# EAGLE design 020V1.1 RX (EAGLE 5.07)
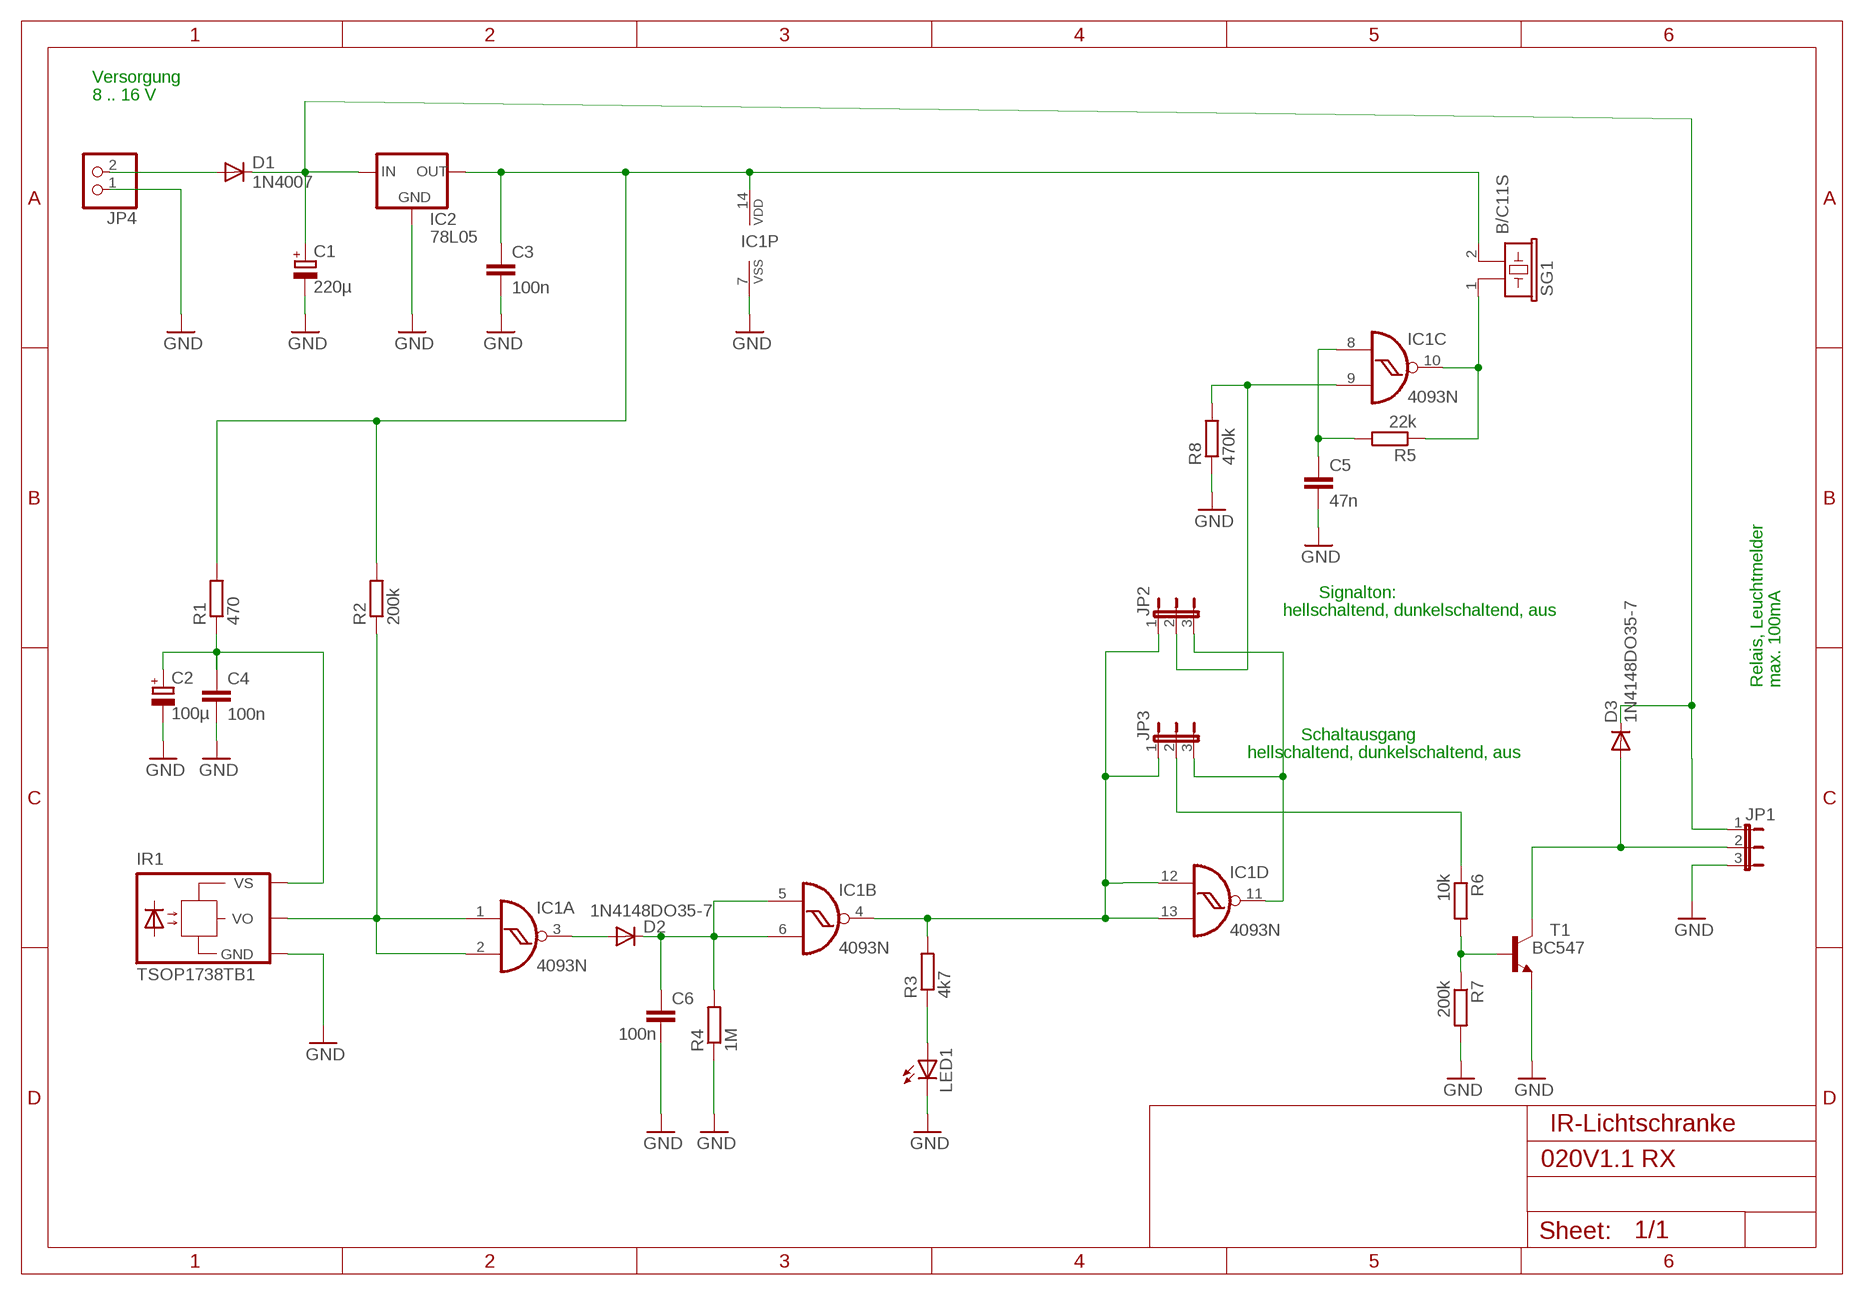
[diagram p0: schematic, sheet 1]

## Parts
C1  220µ  CPOL-EUE2.5-7  [E2,5-7]
C2  100µ  CPOL-EUE2.5-7  [E2,5-7]
C3  100n  C-EU050-025X075  [C050-025X075]
C4  100n  C-EU050-025X075  [C050-025X075]
C5  47n  C-EU050-025X075  [C050-025X075]
C6  100n  C-EU050-025X075  [C050-025X075]
D1  1N4007  1N4004  [DO41-10]
D2  1N4148DO35-7  [DO35-7]
D3  1N4148DO35-7  [DO35-7]
IC1  4093N  [DIL14]
IC2  78L05  78LXX5MM  [TO92-5]
IR1  TSOP1738TB1  [TSOP17_TB1]
JP1  JP2E  [JP2]
JP2  JP2E  [JP2]
JP3  JP2E  [JP2]
JP4  PINHD-1X2  [1X02]
LED1  LED3MM  [LED3MM]
R1  470  R-EU_0204/7  [0204/7]
R2  200k  R-EU_0204/7  [0204/7]
R3  4k7  R-EU_0204/7  [0204/7]
R4  1M  R-EU_0204/7  [0204/7]
R5  22k  R-EU_0204/7  [0204/7]
R6  10k  R-EU_0204/7  [0204/7]
R7  200k  R-EU_0204/7  [0204/7]
R8  470k  R-EU_0204/7  [0204/7]
SG1  B/C11S  [B/C11S]
T1  BC547  [TO92-5]

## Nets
GND: C1.- C2.- C3.2 C4.2 C5.2 C6.2 IC1.7(P:VSS) IC2.2(GND) IR1.GND JP1.3 JP4.1 LED1.K(C) R4.1 R7.2 R8.1 T1.1(E)
N$1: D1.A JP4.2
N$2: C1.+ D1.C D3.C IC2.1(IN) JP1.1
N$3: C3.1 IC1.14(P:VDD) IC2.3(OUT) R1.2 R2.2 SG1.2
N$4: C2.+ C4.1 IR1.VS R1.1
N$5: IC1.1(A:I0) IC1.2(A:I1) IR1.VO R2.1
N$6: D2.A IC1.3(A:O)
N$7: C6.1 D2.C IC1.5(B:I0) IC1.6(B:I1) R4.2
N$8: LED1.A R3.1
N$9: IC1.4(B:O) IC1.12(D:I0) IC1.13(D:I1) JP2.1 JP3.1 R3.2
N$11: C5.1 IC1.8(C:I0) R5.2
N$12: IC1.10(C:O) R5.1 SG1.1
N$13: JP3.2 R6.1
N$14: D3.A JP1.2 T1.3(C)
N$15: IC1.9(C:I1) JP2.2 R8.2
N$16: IC1.11(D:O) JP2.3 JP3.3
N$17: R6.2 R7.1 T1.2(B)

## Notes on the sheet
- Versorgung
- 8 .. 16 V
- Signalton:
- hellschaltend, dunkelschaltend, aus
- Relais, Leuchtmelder | max. 100mA
- Schaltausgang
- hellschaltend, dunkelschaltend, aus
- IR-Lichtschranke

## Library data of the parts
C1 C2 = rcl:CPOL-EU: POLARIZED CAPACITOR, European symbol
C3-C6 = rcl:C-EU: CAPACITOR, European symbol
D1 = diode:1N4004: DIODE
D2 D3 = diode:1N4148: DIODE
IC1 = 40xx:4093: Quad 2-input NAND schmitt trigger
IC2 = armin:78LXX: VOLTAGE REGULATOR
IR1 = telefunken:TSOP17*TB1: TSOP17..TB1 IR Receiver Modules for Remote Control Systems Source: http://www.vishay.com/docs/82042/82042.pdf
JP1-JP3 = jumper:JP2E: JUMPER
JP4 = pinhead:PINHD-1X2: PIN HEADER
LED1 = led:LED: LED
R1-R8 = rcl:R-EU_: RESISTOR, European symbol
SG1 = buzzer:B/C11S: BUZZER
T1 = armin:BC547: NPN TRANSISTOR

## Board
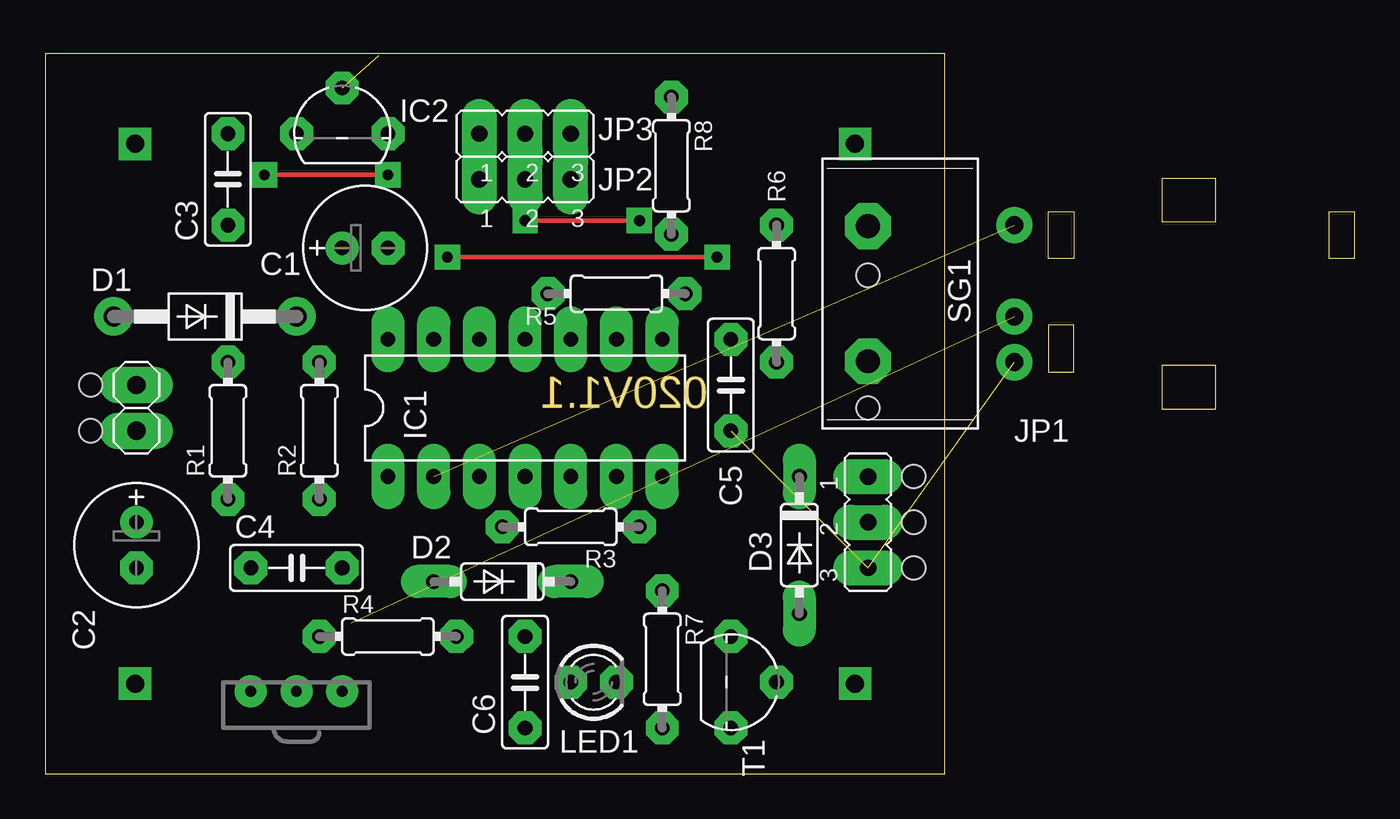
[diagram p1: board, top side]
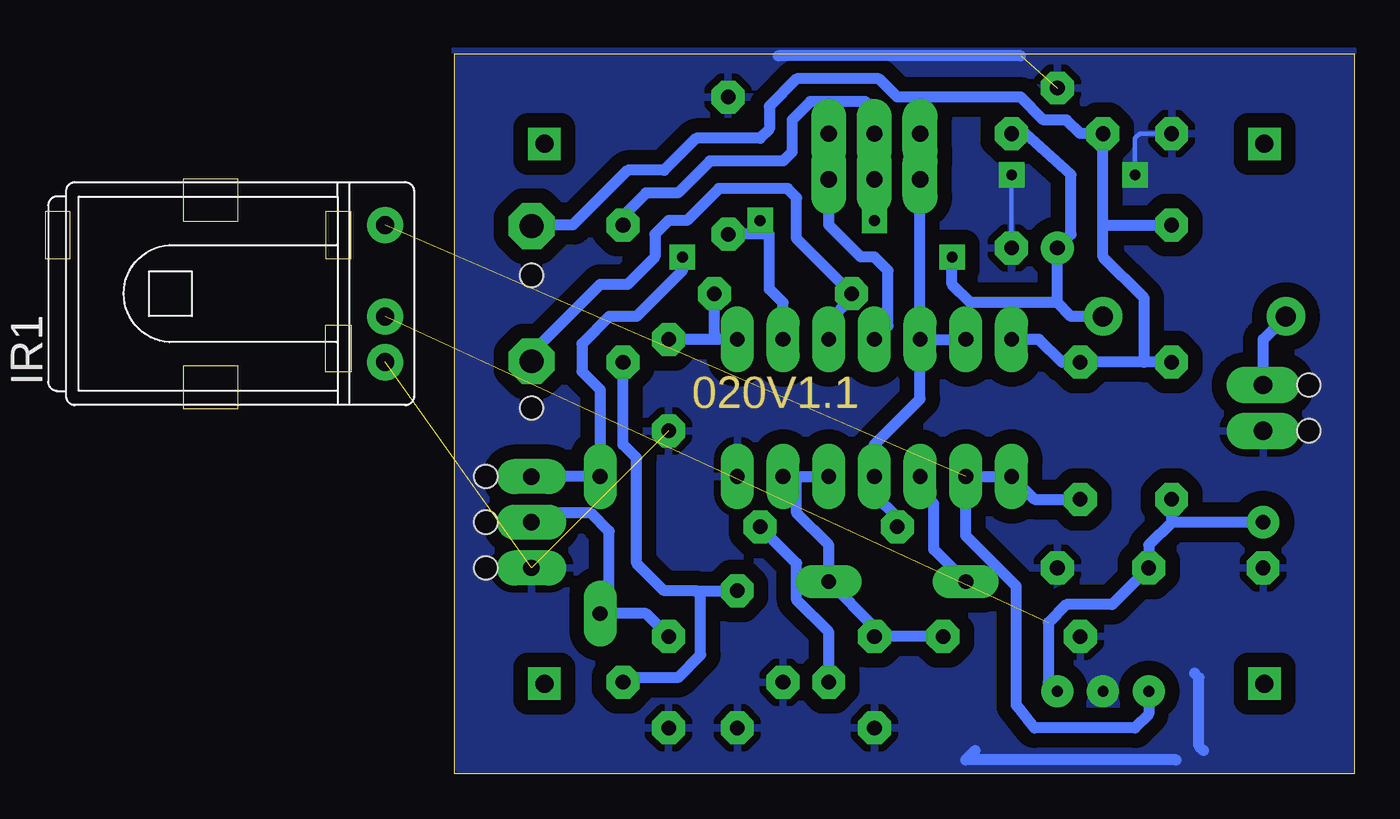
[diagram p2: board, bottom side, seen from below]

Size 72.75 x 40 mm. Coordinates in mm from the lower left corner, seen from the top.
Outline: 0,0 50,0 50,40 0,40 0,0
Copper layers (1*16): Top 0.035mm / dielectric 1.5mm / Bottom 0.035mm
Design rules "default *": minimum track width 10mil, minimum drill 24mil, track to track 32mil, track to pad 32mil, pad to pad 25mil, via to via 25mil, smd to smd 8mil, copper to edge 1mil, drill to drill 8mil, minimum pad ring 20mil, minimum via ring 16mil, stop-mask expansion 4mil, vias tented up to drill 0mil, thermal gap 16mil
Holes 1.3 mm at 2.54,21.59 2.54,19.05 45.72,27.69 45.72,20.32 48.26,13.97 48.26,11.43 48.26,13.97 48.26,16.51

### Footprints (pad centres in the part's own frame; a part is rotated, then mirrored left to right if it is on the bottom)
E2,5-7 = drill 0.813 pad 1.6 round: + -1.27,0 | drill 0.813 pad 1.6 octagon: - 1.27,0
C050-025X075 = drill 0.813 octagon: 1 -2.54,0; 2 2.54,0
DO41-10 = drill 1.118 round: A 5.08,0; C -5.08,0
DO35-7 = drill 0.813 long: A 3.81,0; C -3.81,0
DIL14 = drill 0.813 long: 1 -7.62,-3.81; 2 -5.08,-3.81; 3 -2.54,-3.81; 4 0,-3.81; 5 2.54,-3.81; 6 5.08,-3.81; 7 7.62,-3.81; 8 7.62,3.81; 9 5.08,3.81; 10 2.54,3.81; 11 0,3.81; 12 -2.54,3.81; 13 -5.08,3.81; 14 -7.62,3.81
TO92-5 = drill 0.813 octagon: 1 2.54,0; 2 0,2.54; 3 -2.54,0
TSOP17_TB1 = drill 1 pad 1.676 round: GND 0,-3.81; VO 0,3.81; VS 0,-1.27
JP2 = drill 0.914 long: 1 -2.54,0; 2 0,0; 3 2.54,0
1X02 = drill 1.016 long: 1 -1.27,0; 2 1.27,0
LED3MM = drill 0.813 octagon: A -1.27,0; K 1.27,0
0204/7 = drill 0.813 octagon: 1 -3.81,0; 2 3.81,0
B/C11S = drill 1.321 pad 2.54 octagon: 1 -3.759,0; 2 3.759,0

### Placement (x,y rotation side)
C1  17.78,29.21 0 top
C2  5.08,12.7 270 top
C3  10.16,33.02 90 top
C4  13.97,11.43 0 top
C5  38.1,21.59 270 top
C6  26.67,5.08 270 top
D1  8.89,25.4 180 top
D2  25.4,10.67 180 top
D3  41.91,12.7 270 top
IC1  26.67,20.32 0 top
IC2  16.51,35.56 0 top
IR1  53.85,26.67 0 bottom
JP1  45.72,13.97 270 top
JP2  26.67,33.02 0 top
JP3  26.67,35.56 0 top
JP4  5.08,20.32 90 top
LED1  30.48,5.08 0 top
R1  10.16,19.05 90 top
R2  15.24,19.05 90 top
R3  29.21,13.72 180 top
R4  19.05,7.62 0 top
R5  31.75,26.67 0 top
R6  40.64,26.67 270 top
R7  34.29,6.35 270 top
R8  34.8,33.78 270 top
SG1  45.72,26.67 90 top
T1  38.1,5.08 270 top

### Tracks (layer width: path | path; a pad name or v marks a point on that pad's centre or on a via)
GND  (via drill 0.6, 0.6 pad 1.78)  (3 unrouted)
  Top 0.254: v12.19,33.27 v19.05,33.27
  Bottom 0.254: v19.05,33.27 C1.- | v12.19,33.27 12.19,35.31 11.94,35.56 C3.2
  Bottom 0.61: 21.08,1.27 21.59,0.76 9.91,0.76 | 8.89,5.59 8.64,5.33 8.64,1.52 8.38,1.27 | 18.54,39.88 32,39.88
  other vias: 13.97,4.57
  pour Bottom: 0,40.13 50.04,40.13 50.04,0.51 49.78,0.25 0,0.25 0,37.59 0.25,37.85
  pour Bottom: 24.89,21.08 26.42,19.56 36.83,19.3 37.34,21.08 37.34,23.11 24.89,23.11
N$1
  Bottom 0.61: JP4.2 5.08,24.13 D1.A
N$2  (via drill 0.6)
  Top 0.254: v22.35,28.7 v37.34,28.7
  Bottom 0.61: IC2.1 18.29,35.56 15.75,33.27 15.75,29.97 C1.+ 16.51,26.16 | 16.51,26.16 15.75,25.4 D1.C | v37.34,28.7 37.34,27.94 39.88,25.4 41.4,25.4 42.93,23.88 42.93,22.35 41.91,21.34 D3.C JP1.1 | 16.51,26.16 21.34,26.16 22.35,27.18 v22.35,28.7
N$3
  Bottom 0.61: 11.68,22.86 R2.2 16.26,22.86 17.53,24.13 IC1.14 | 13.97,30.48 13.97,28.7 11.68,26.42 11.68,22.86 | 13.97,30.48 IC2.3 15.24,35.56 16,36.32 17.27,36.32 18.54,37.59 25.4,37.59 26.42,38.61 30.99,38.61 32.51,37.08 32.51,35.81 33.02,35.31 36.58,35.31 38.35,33.53 40.39,33.53 43.43,30.48 45.67,30.48 SG1.2 | R1.2 11.68,22.86 | 13.97,30.48 C3.1
N$4  (via drill 0.6 pad 1.78)  (1 unrouted)
  Bottom 0.61: C2.+ 10.16,13.97 | 10.16,13.97 R1.1 | 10.16,13.97 11.43,12.7 C4.1 13.46,9.4 16,9.4 17.02,8.38 17.02,5.08 v16.51,4.57
N$5  (via drill 0.6 pad 1.78)  (1 unrouted)
  Bottom 0.61: R2.1 17.78,15.24 IC1.1 IC1.2 21.59,13.21 18.8,10.41 18.8,3.81 17.78,2.54 12.19,2.54 11.43,3.3 v11.43,4.57
N$6
  Bottom 0.61: IC1.3 24.13,15.75 23.37,14.99 23.37,12.45 D2.A
N$7
  Bottom 0.61: R4.2 C6.1 26.67,8.13 D2.C 29.21,12.7 30.99,14.48 30.99,16.26 31.24,16.51 | 31.24,16.51 IC1.5 | 31.24,16.51 IC1.6
N$8
  Bottom 0.61: R3.1 30.99,11.68 30.99,9.65 29.21,7.87 LED1.A
N$9
  Bottom 0.61: JP3.1 JP2.1 IC1.12 | IC1.12 IC1.13 | IC1.12 24.13,20.83 26.67,18.29 IC1.4 26.67,15.49 25.4,14.22 R3.2
N$10  (via drill 1)
  other vias: 5,5
N$11
  Bottom 0.61: IC1.8 35.31,24.13 | 35.31,24.13 C5.1 | R5.2 35.56,24.38 35.31,24.13
N$12
  Bottom 0.61: IC1.10 29.21,25.15 27.94,26.42 R5.1 30.99,29.72 30.99,32 31.5,32.51 35.31,32.51 37.08,30.73 38.1,30.73 38.86,29.97 38.86,28.7 40.39,27.18 41.91,27.18 45.72,23.37 SG1.1
N$13
  Bottom 0.61: JP3.2 26.67,36.83 27.18,37.34 30.23,37.34 31.24,36.32 31.24,34.54 31.75,34.04 35.81,34.04 37.59,32.26 39.37,32.26 40.64,30.99 R6.1
N$14
  Bottom 0.61: T1.3 39.37,8.89 D3.A 41.4,9.4 41.4,13.46 42.42,14.48 45.21,14.48 JP1.2
N$15  (via drill 0.6)
  Top 0.254: v33.02,30.73 v26.67,30.73
  Bottom 0.61: v26.67,30.73 JP2.2 | 32.51,29.97 32.51,26.92 31.75,26.16 IC1.9 | 32.51,29.97 R8.2 | 32.51,29.97 v33.02,30.73
N$16
  Bottom 0.61: JP3.3 JP2.3 29.21,30.48 27.43,28.7 26.67,28.7 25.91,27.94 25.91,24.89 IC1.11
N$17
  Bottom 0.61: R6.2 40.64,18.29 39.88,17.53 39.88,11.68 38.35,10.16 36.58,10.16 | 36.58,10.16 R7.1 | 36.58,10.16 36.32,9.91 36.32,6.6 37.59,5.33 40.13,5.33 40.39,5.08 T1.2
N$18  (via drill 1)
  other vias: 45,5
N$19  (via drill 1)
  other vias: 45,35
N$20  (via drill 1)
  other vias: 5,35

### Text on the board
Dimension: 020V1.1
tDocu: dunkel/hellschaltend | +8..16V | GND | + Relais | OUT | GND | SFH5110-36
